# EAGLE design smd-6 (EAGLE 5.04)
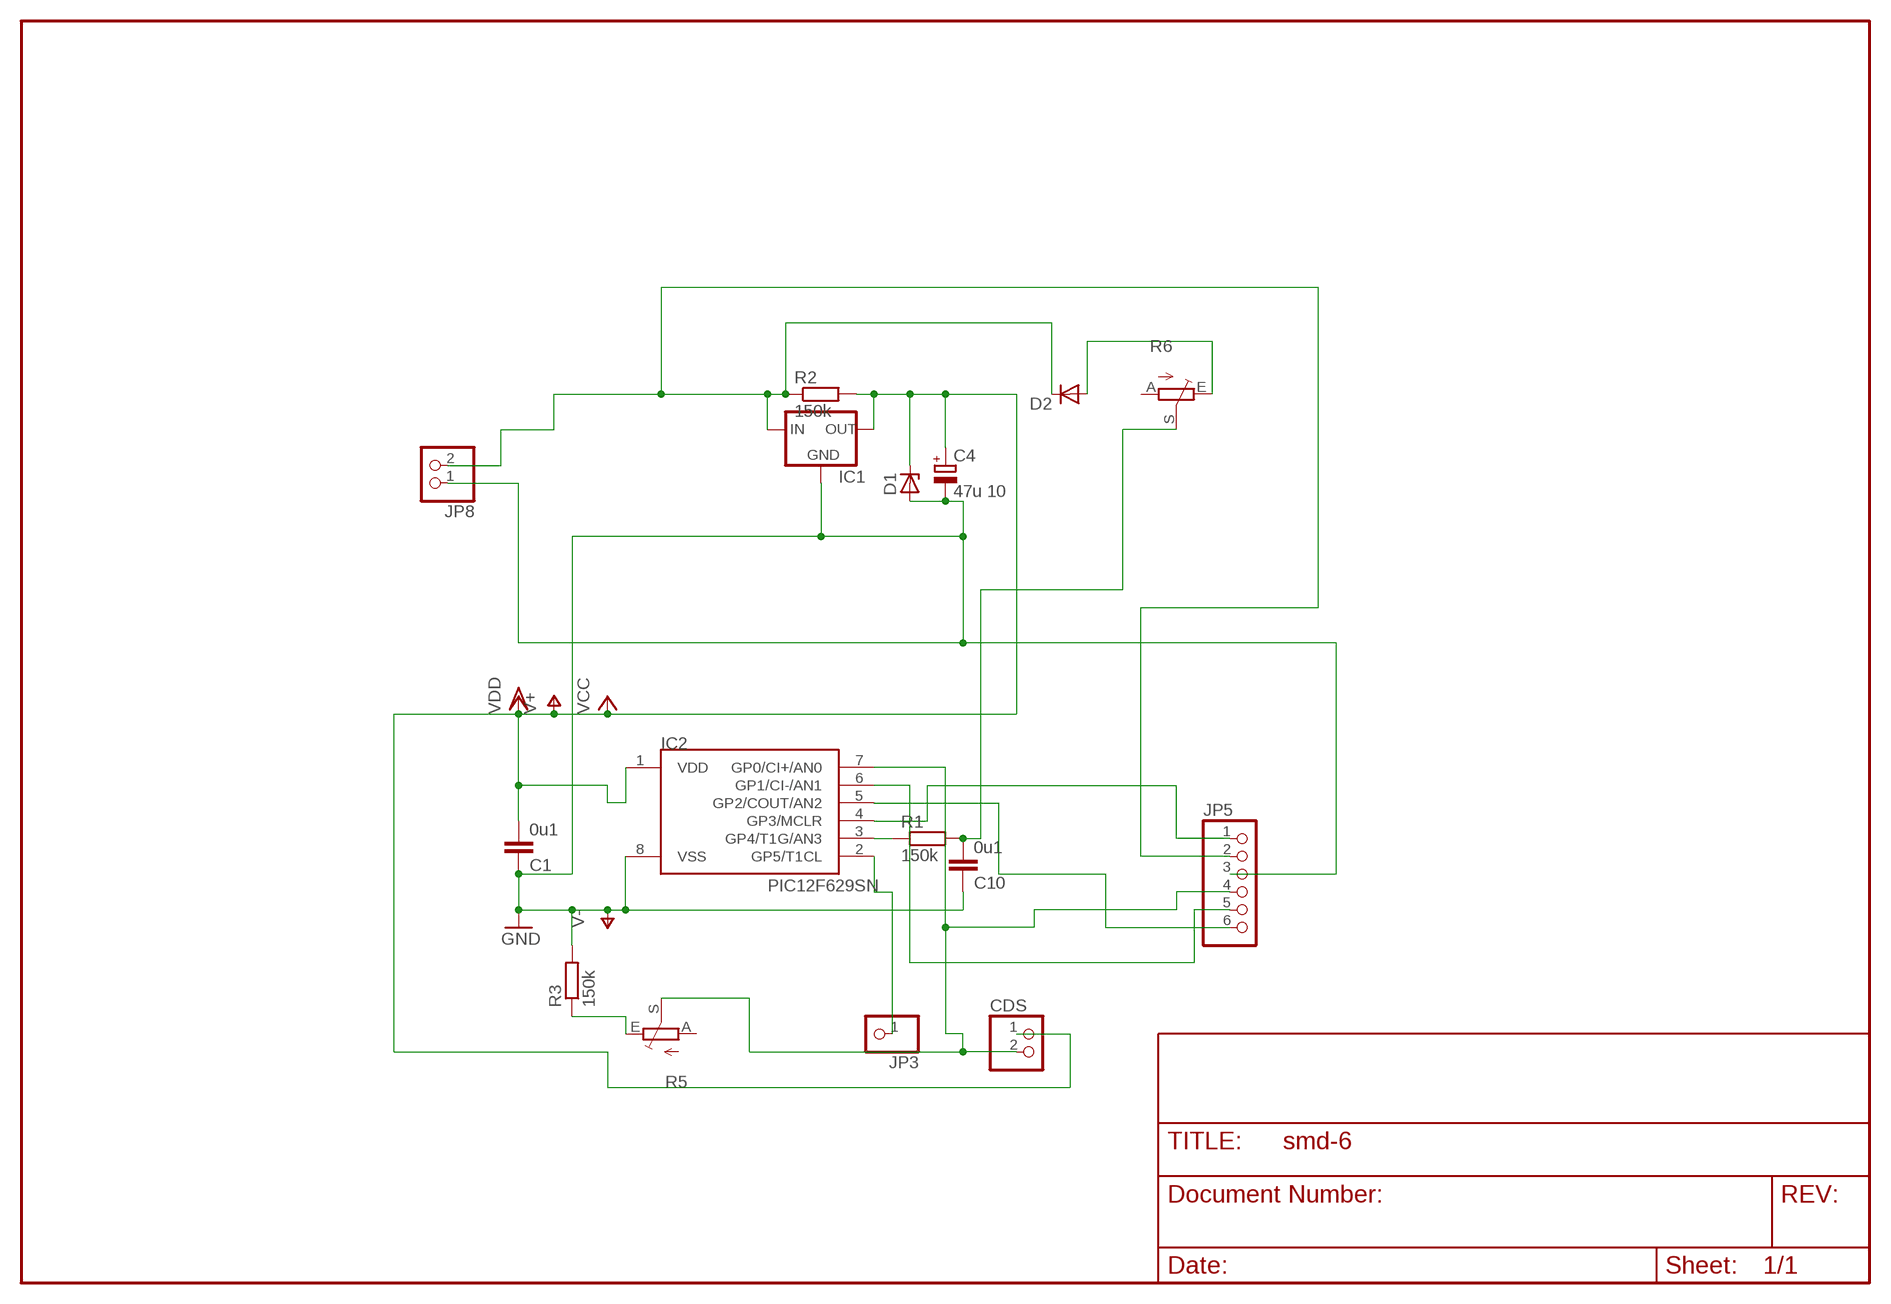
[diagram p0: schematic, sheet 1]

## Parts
C1  0u1  C-EUC1206  [C1206]
C4  47u 10  CPOL-EUE2.5-6  [E2,5-6]
C10  0u1  C-EUC1206  [C1206]
CDS  PINHD-1X2  [1X02]
D1  ZENER-DIODESOT23  [SOT23]
D2  DIODE-D-2.5  [D-2.5]
IC1  78LXX  [78LXX]
IC2  PIC12F629SN  [SO-08]
JP3  PINHD-1X1  [1X01]
JP5  PINHD-1X6  [1X06]
JP8  PINHD-1X2  [1X02]
R1  150k  R-EU_0204/2V  [0204V]
R2  150k  R-EU_0204/2V  [0204V]
R3  150k  R-EU_0207/12  [0207/12]
R5  TRIM_EU-CA6V  [CA6V]
R6  TRIM_EU-CA6V  [CA6V]

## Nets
CDS: IC2.2(GP5/T1CL) JP3.1
N$1: C10.2 R1.2 R6.S
N$2: IC2.5(GP2/COUT/AN2) JP5.6
N$3: IC2.4(GP3/MCLR) JP5.1
N$4: CDS.2 IC2.7(GP0/CI+/AN0) JP5.4 R5.S
N$5: R3.1 R5.E
N$7: D2.A R6.E
N$8: IC2.3(GP4/T1G/AN3) R1.1
N$9: D2.C IC1.IN JP5.2 JP8.2 R2.1
N$15: IC2.6(GP1/CI-/AN1) JP5.5
V+: C1.2 C4.+ CDS.1 D1.3(C) IC1.OUT IC2.1(VDD) R2.2 ; supply symbol labelled VCC, VDD
V-: C1.1 C4.- C10.1 D1.1(A) IC1.GND IC2.8(VSS) JP5.3 JP8.1 R3.2 ; supply symbol labelled GND
Unconnected: R5.A R6.A

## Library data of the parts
C1 C10 = rcl:C-EU: CAPACITOR, European symbol
C4 = rcl:CPOL-EU: POLARIZED CAPACITOR, European symbol
CDS JP8 = pinhead:PINHD-1X2: PIN HEADER
D1 = diode-1:ZENER-DIODE: Z-Diode
D2 = diode-1:DIODE-: DIODE
IC1 = v-reg:78LXX: VOLTAGE REGULATOR
IC2 = microchip-3:PIC12F6*: uPC nW 1k Program Flash memory 2x Timer Comparator 10b A/D converter/ 4xIN
JP3 = pinhead:PINHD-1X1: PIN HEADER
JP5 = pinhead(2):PINHD-1X6: PIN HEADER
R1-R3 = rcl:R-EU_: RESISTOR, European symbol
R5 R6 = pot:TRIM_EU-: POTENTIOMETER

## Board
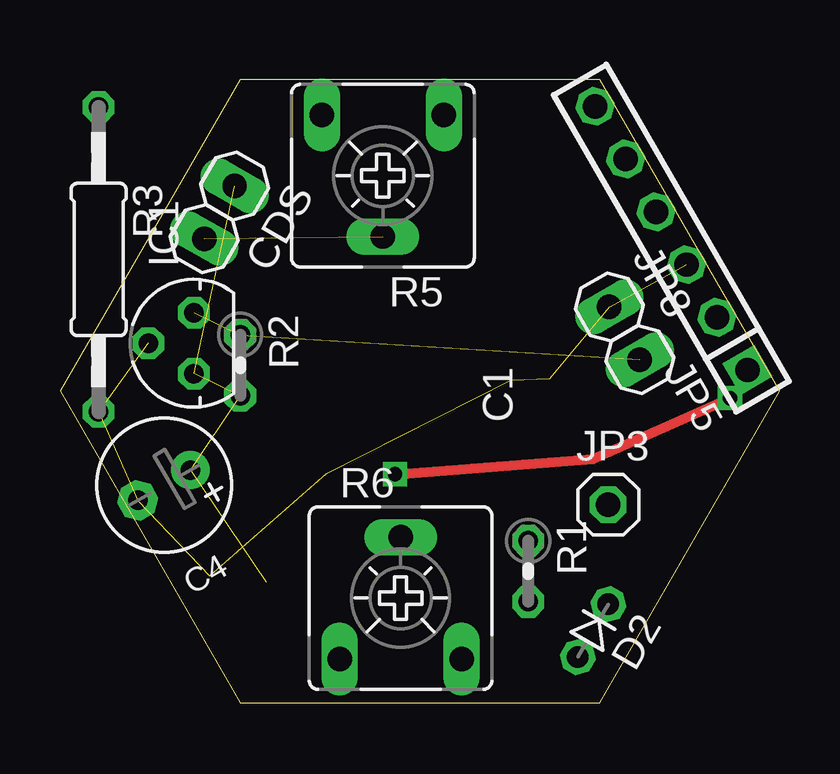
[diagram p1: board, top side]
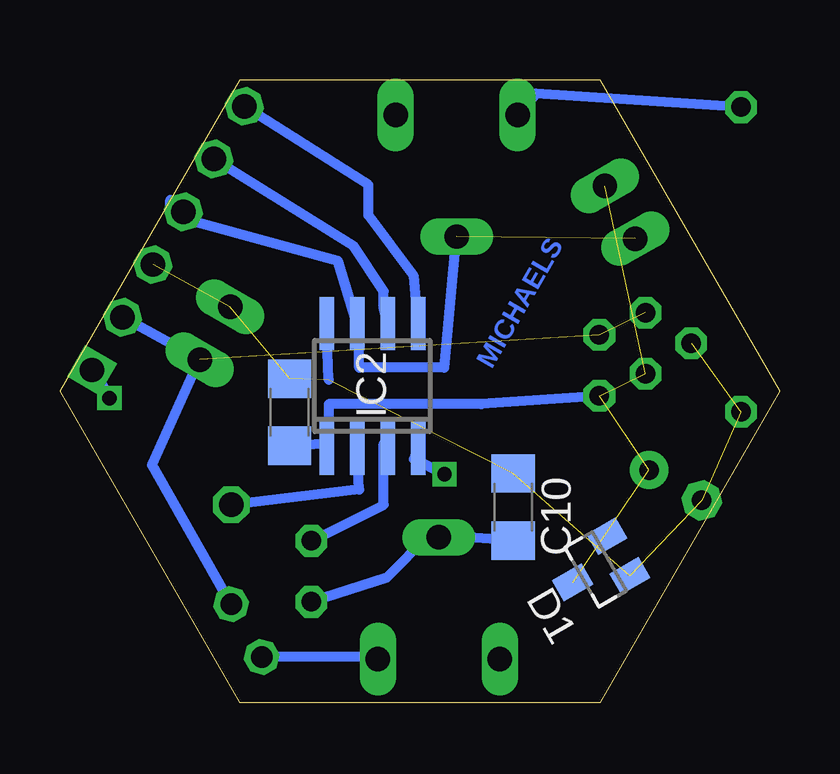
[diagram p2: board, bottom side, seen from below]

Size 30 x 25.98 mm. Coordinates in mm from the lower left corner, seen from the top.
Outline: 7.5,0 22.5,0 30,12.99 22.5,25.98 7.5,25.98 0,12.99 7.5,0
Copper layers (1*16): Top 0.035mm / dielectric 1.5mm / Bottom 0.035mm
Design rules "default *": minimum track width 10mil, minimum drill 24mil, track to track 8mil, track to pad 8mil, pad to pad 8mil, via to via 8mil, smd to smd 8mil, copper to edge 10mil, drill to drill 8mil, minimum pad ring 10mil, minimum via ring 8mil, stop-mask expansion 4mil, vias tented up to drill 0mil, thermal gap 10mil

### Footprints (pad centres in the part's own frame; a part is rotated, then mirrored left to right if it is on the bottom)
C1206 = smd 1.6 x 1.8: 1 -1.4,0; 2 1.4,0
E2,5-6 = drill 0.813 pad 1.6 round: + -1.27,0 | drill 0.813 pad 1.6 octagon: - 1.27,0
1X02 = drill 1.016 long: 1 -1.27,0; 2 1.27,0
SOT23 = smd 1 x 1.4: 1 -0.95,-1.1; 2 0.95,-1.1; 3 0,1.1
D-2.5 = drill 0.9 octagon: A 1.27,0; C -1.27,0
78LXX = drill 0.813 octagon: GND 0,1.905; IN 1.27,0; OUT -1.27,0
SO-08 = smd 0.6 x 2.2: 1 -1.905,-2.6; 2 -0.635,-2.6; 3 0.635,-2.6; 4 1.905,-2.6; 5 1.905,2.6; 6 0.635,2.6; 7 -0.635,2.6; 8 -1.905,2.6
1X01 = drill 1.016 octagon: 1 0,0
1X06 = drill 1.016 square: 1 -6.35,0 | drill 1.016 octagon: 2 -3.81,0; 3 -1.27,0; 4 1.27,0; 5 3.81,0; 6 6.35,0
0204V = drill 0.813 octagon: 1 -1.27,0; 2 1.27,0
0207/12 = drill 0.813 octagon: 1 -6.35,0; 2 6.35,0
CA6V = drill 1.016 long: A -2.54,-2.54; E 2.54,-2.54; S 0,2.54

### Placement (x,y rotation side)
C1  20.42,12.11 270 bottom
C4  4.34,9.07 210 top
C10  11.1,8.16 270 bottom
CDS  6.65,20.44 240 top
D1  7.67,5.57 120 bottom
D2  22.23,3 240 top
IC1  5.59,14.99 90 top
IC2  16.98,13.2 0 bottom
JP3  22.86,8.26 0 top
JP5  25.48,19.37 120 top
JP8  23.54,15.4 300 top
R1  19.52,5.48 270 top
R2  7.51,14.06 270 top
R3  1.61,18.48 270 top
R5  13.46,21.97 180 top
R6  14.2,4.36 0 top

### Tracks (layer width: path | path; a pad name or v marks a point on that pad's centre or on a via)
CDS
  Bottom 0.406: IC2.2 17.53,8.89 JP3.1
N$1
  Bottom 0.406: 14.61,6.99 R6.S | C10.2 14.61,6.99 | R1.2 16.38,5.21 14.61,6.99
N$2
  Bottom 0.406: JP5.6 17.14,21.59 17.14,20.32 15.24,17.78 IC2.5
N$3  (via drill 0.6)
  Top 0.406: v13.97,9.53 22.23,10.16 v27.94,12.7
  Bottom 0.406: IC2.4 15.24,10.16 v13.97,9.53 | JP5.1 28.57,13.97 v27.94,12.7
N$4  (1 unrouted)
  Bottom 0.406: JP5.4 24.77,20.32 25.4,20.95 25.4,20.32 18.41,18.41 IC2.7 17.53,14.86 17.53,13.97 13.97,13.97 R5.S
N$5
  Bottom 0.406: R3.1 10.16,25.4 R5.E
N$7
  Bottom 0.406: R6.E 17.14,1.91 D2.A
N$8
  Bottom 0.406: R1.1 16.51,8.26 16.51,10.79 IC2.3
N$9  (2 unrouted)
  Bottom 0.406: D2.C 26.16,9.91 JP8.2 JP5.2
N$15
  Bottom 0.406: JP5.5 17.78,19.05 16.51,17.14 16.51,16.51 IC2.6
V+  (4 unrouted)
  Bottom 0.406: 20.32,10.79 C1.2 19.05,10.79 IC2.1 18.8,11.18 18.8,12.45 12.45,12.45 R2.2
V-  (8 unrouted)
  Bottom 0.406: 18.8,13.46 IC2.8

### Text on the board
Bottom: MICHAELS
